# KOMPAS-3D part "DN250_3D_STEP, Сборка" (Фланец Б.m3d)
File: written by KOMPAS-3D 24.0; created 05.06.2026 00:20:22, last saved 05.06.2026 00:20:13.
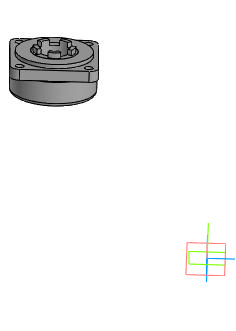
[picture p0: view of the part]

Document properties: Автор: R2D2; Полное имя файла: E:\Работа\Зайцев\!готово\GVWR2121M-2W-F-ОСТ Задвижка клиновая с выдвижным штоком Ду50-300 Ру16\DN250\Исходные материалы\Фланец Б.m3d

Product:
- Part/product: DN250_3D_STEP  | designation Сборка
    Масса: 5.389074

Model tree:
1. Операция без истории:1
